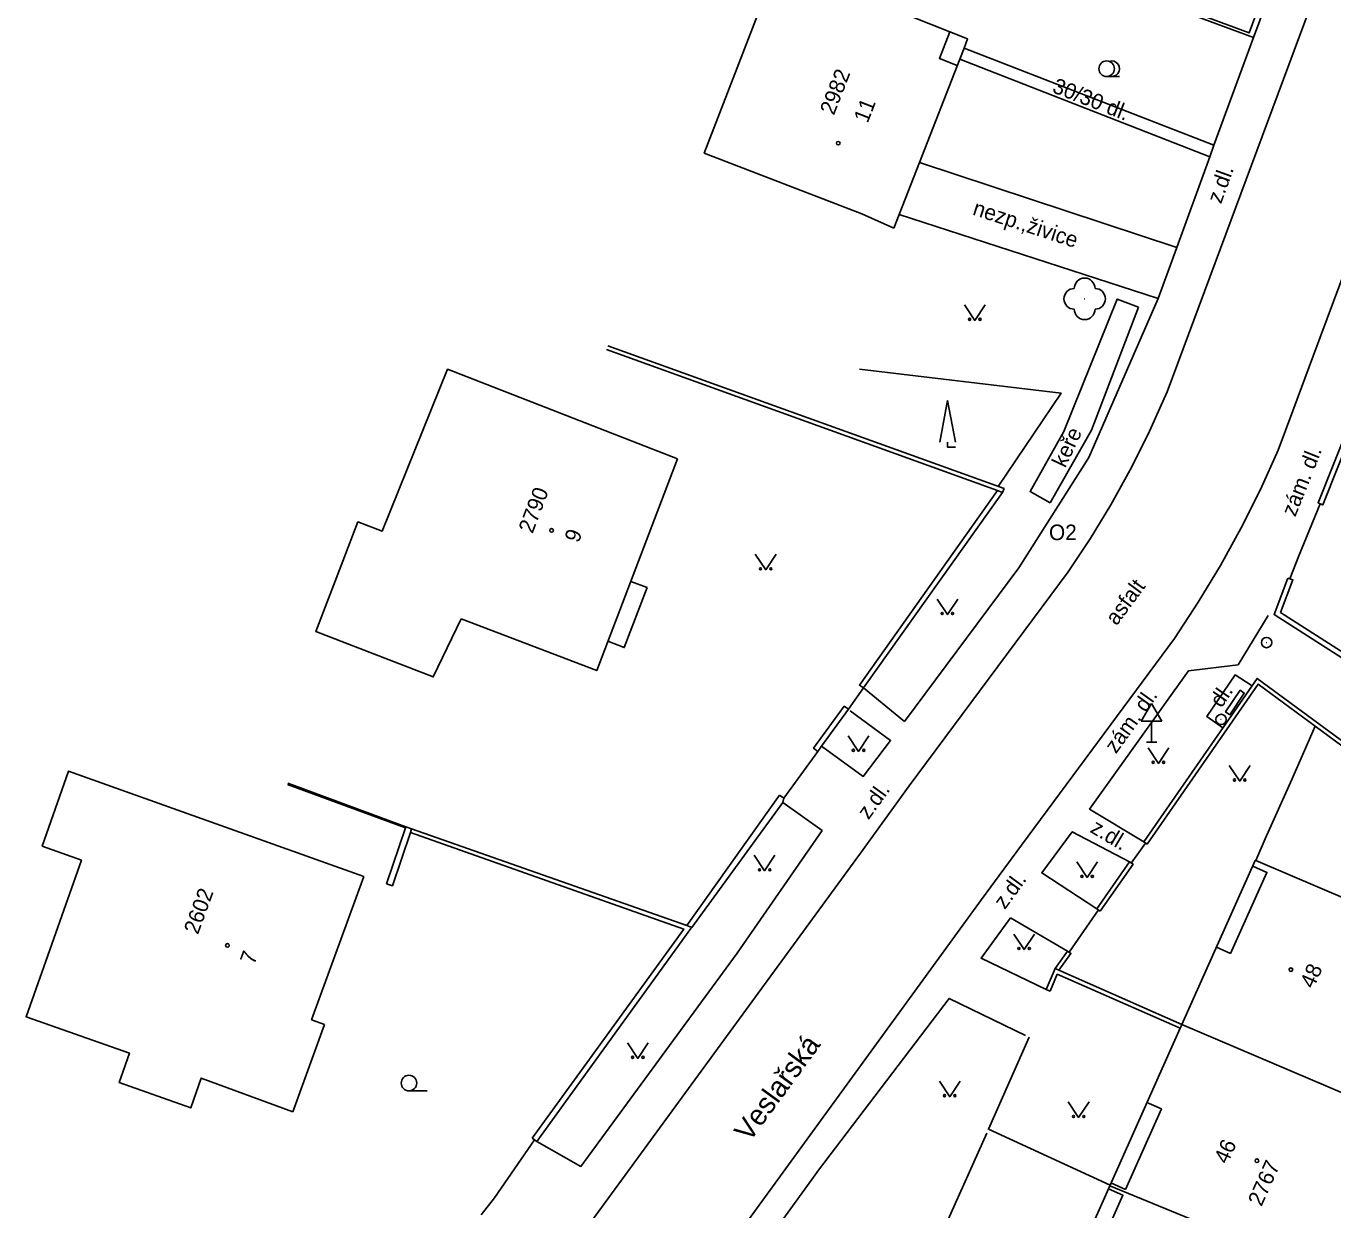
# Model space of a CAD drawing. Extents: x -584400 to -581602, y -1210894 to -1208793.
# Drawn here: x -583267.9 to -583204.8, y -1210484 to -1210426.9 of the extents above; entities that cross this region are included whole.
import ezdxf

# ---------------------------------------------------------------- set-up
doc = ezdxf.new("R2010")
doc.units = 0
for name, color, linetype in [('BUDOVY_MĚŘ', 7, 'Continuous'), ('NÁZVY_ULIC_TOK_SMĚR', 7, 'Continuous'), ('POMOC_POPIS', 7, 'Continuous'), ('ROZHRANÍ_PLOCH', 7, 'Continuous'), ('ZELEŇ', 7, 'Continuous'), ('ZN_BUDOV', 7, 'Continuous'), ('ZN_DOPLŇKOVÉ', 7, 'Continuous'), ('ZN_KULTUR', 7, 'Continuous'), ('Č_POPIS_EVID', 7, 'Continuous')]:
    doc.layers.add(name, color=color, linetype=linetype)

msp = doc.modelspace()

# ---------------------------------------------------------------- linework, layer by layer
at = {"layer": 'BUDOVY_MĚŘ'}
for points in [[(-583223.3, -1210427.13), (-583231.61, -1210423.81), (-583235.14, -1210432.98), (-583227.54, -1210435.91), (-583226, -1210436.6)], [(-583222.61, -1210427.91), (-583222.44, -1210427.47), (-583223.3, -1210427.13)], [(-583222.82, -1210428.45), (-583222.61, -1210427.91)], [(-583226, -1210436.6), (-583225.74, -1210435.94), (-583224.76, -1210433.43), (-583222.82, -1210428.45)], [(-583236.44, -1210447.73), (-583247.53, -1210443.41), (-583250.69, -1210451.22), (-583251.85, -1210450.77), (-583252.58, -1210452.66), (-583253.89, -1210456.06), (-583248.22, -1210458.25), (-583246.87, -1210455.45)], [(-583246.87, -1210455.45), (-583240.33, -1210457.94), (-583236.44, -1210447.73)], [(-583251.57, -1210467.88), (-583265.81, -1210462.79), (-583267.08, -1210466.41), (-583265.19, -1210467.08), (-583267.86, -1210474.64), (-583262.87, -1210476.4), (-583263.37, -1210477.82), (-583259.92, -1210479.04), (-583259.41, -1210477.6), (-583255, -1210479.23)], [(-583212.14, -1210475.1), (-583212.1, -1210475.01), (-583208.56, -1210467.1), (-583208.53, -1210467.11)], [(-583208.53, -1210467.11), (-583197.95, -1210471.63), (-583201.46, -1210479.55)], [(-583255, -1210479.23), (-583253.47, -1210475.02), (-583254.09, -1210474.79), (-583251.57, -1210467.88)], [(-583215.56, -1210482.76), (-583212.18, -1210475.19)], [(-583212.18, -1210475.19), (-583212.14, -1210475.1)], [(-583201.46, -1210479.55), (-583212.1, -1210475.01)], [(-583218.9, -1210490.28), (-583215.64, -1210482.94), (-583215.58, -1210482.8)], [(-583215.58, -1210482.8), (-583215.56, -1210482.76)], [(-583204.85, -1210487.2), (-583215.58, -1210482.8)]]:
    msp.add_lwpolyline(points, dxfattribs=at)
at = {"layer": 'ROZHRANÍ_PLOCH'}
for points in [[(-583176.25, -1210363.59), (-583205.75, -1210442.72)], [(-583212.81, -1210444.5), (-583187.79, -1210377.24)], [(-583222.94, -1210428.75), (-583223.8, -1210428.41), (-583223.3, -1210427.13)], [(-583210.55, -1210432.6), (-583222.61, -1210427.91)], [(-583208.64, -1210427.4), (-583210.55, -1210432.6)], [(-583210.75, -1210433.16), (-583222.82, -1210428.45)], [(-583210.55, -1210432.6), (-583210.75, -1210433.16)], [(-583212.34, -1210437.54), (-583224.76, -1210433.43)], [(-583210.75, -1210433.16), (-583212.34, -1210437.54)], [(-583213.25, -1210440), (-583225.74, -1210435.94)], [(-583212.34, -1210437.54), (-583213.25, -1210440)], [(-583213.25, -1210440), (-583216.59, -1210447.66), (-583219.97, -1210452.98), (-583225.48, -1210460.4)], [(-583206.75, -1210445.41), (-583205.75, -1210442.72)], [(-583217.59, -1210453.18), (-583216.52, -1210451.58), (-583215.52, -1210449.94), (-583214.59, -1210448.26), (-583213.72, -1210446.54), (-583212.81, -1210444.5)], [(-583212.45, -1210456.39), (-583211.31, -1210454.65), (-583210.24, -1210452.87), (-583209.24, -1210451.06), (-583208.31, -1210449.2), (-583207.45, -1210447.31), (-583206.75, -1210445.41)], [(-583217.59, -1210453.18), (-583225.26, -1210463.51), (-583227.61, -1210466.75), (-583239.44, -1210482.95), (-583241.75, -1210486.11), (-583261.42, -1210513.13), (-583262.5, -1210514.29)], [(-583238.69, -1210453.64), (-583237.9, -1210453.94)], [(-583239.8, -1210456.53), (-583239, -1210456.83), (-583237.9, -1210453.94)], [(-583209.39, -1210457.66), (-583207.94, -1210455.29)], [(-583212.45, -1210456.39), (-583219.83, -1210466.36), (-583221.77, -1210468.99)], [(-583213.94, -1210466.21), (-583216.55, -1210464.62), (-583211.78, -1210457.96), (-583209.39, -1210457.66)], [(-583210.13, -1210460.7), (-583210.9, -1210460.15), (-583209.53, -1210458.15), (-583208.71, -1210458.68)], [(-583225.48, -1210460.4), (-583227.46, -1210458.78)], [(-583228.1, -1210459.88), (-583226.15, -1210461.32), (-583227.47, -1210463.05), (-583229.49, -1210461.59)], [(-583231.35, -1210464.31), (-583229.46, -1210465.66), (-583233.56, -1210471.58), (-583241.09, -1210481.86), (-583243.22, -1210480.66)], [(-583216.2, -1210469.44), (-583218.86, -1210467.7), (-583217.39, -1210465.72), (-583214.62, -1210467.17)], [(-583209.75, -1210471.59), (-583208, -1210467.68), (-583208.68, -1210467.37)], [(-583221.77, -1210468.99), (-583238.84, -1210492.46), (-583241.63, -1210496.27), (-583249.18, -1210506.55), (-583256.63, -1210516.77)], [(-583220.36, -1210469.87), (-583221.79, -1210471.81), (-583218.65, -1210473.32)], [(-583217.61, -1210471.47), (-583220.36, -1210469.87)], [(-583209.75, -1210471.59), (-583210.43, -1210471.29)], [(-583219.64, -1210475.55), (-583223.33, -1210473.76), (-583229.63, -1210482.04), (-583229.95, -1210482.49)], [(-583214.82, -1210482.97), (-583213.09, -1210479.09), (-583213.79, -1210478.78)], [(-583227.53, -1210493.6), (-583235.45, -1210490.08), (-583229.95, -1210482.49)], [(-583214.82, -1210482.97), (-583215.52, -1210482.66)], [(-583216.57, -1210486.92), (-583214.94, -1210483.25), (-583215.64, -1210482.94)]]:
    msp.add_lwpolyline(points, dxfattribs=at)
at = {"layer": 'ZELEŇ'}
for points in [[(-583218.46, -1210449.85), (-583219.42, -1210449.31), (-583217.79, -1210446.41), (-583215.22, -1210440.02), (-583214.19, -1210440.41)], [(-583220.96, -1210449.06), (-583217.93, -1210444.56), (-583227.65, -1210443.4)]]:
    msp.add_lwpolyline(points, dxfattribs=at)
msp.add_circle((-583216.79, -1210440.01), 0.0005, dxfattribs=at)
for centre, start, end in [((-583216.79, -1210439.51), 0, 179.99999), ((-583217.29, -1210440.01), 89.99999, 269.99999), ((-583216.29, -1210440.01), 270, 89.99999), ((-583216.79, -1210440.51), 179.99999, 359.99999)]:
    msp.add_arc(centre, 0.5, start, end, dxfattribs=at)
at = {"layer": 'ZN_BUDOV'}
for centre in [(-583228.68, -1210432.5), (-583242.51, -1210451.18), (-583258.15, -1210471.2), (-583206.84, -1210472.37), (-583208.48, -1210481.59)]:
    msp.add_circle(centre, 0.0875, dxfattribs=at)
at = {"layer": 'ZN_DOPLŇKOVÉ'}
for p, q in [((-583213.56, -1210459.524), (-583214.06, -1210460.39)), ((-583213.56, -1210459.524), (-583213.06, -1210460.39)), ((-583214.06, -1210460.39), (-583213.06, -1210460.39)), ((-583213.56, -1210461.39), (-583213.56, -1210460.39)), ((-583213.81, -1210461.39), (-583213.31, -1210461.39))]:
    msp.add_line(p, q, dxfattribs=at)
for points in [[(-583218.05, -1210423.91), (-583208.64, -1210427.4), (-583205.74, -1210419.58), (-583206, -1210419.48)], [(-583218, -1210423.79), (-583208.85, -1210427.18), (-583206, -1210419.48)], [(-583214.19, -1210440.41), (-583216.46, -1210446.34), (-583218.46, -1210449.85)], [(-583220.99, -1210449.26), (-583239.86, -1210442.46)], [(-583220.68, -1210449.16), (-583239.8, -1210442.28)], [(-583204.08, -1210446.22), (-583205.53, -1210449.85), (-583205.42, -1210449.9)], [(-583203.85, -1210446.31), (-583205.3, -1210449.95), (-583205.42, -1210449.9)], [(-583220.99, -1210449.26), (-583227.66, -1210458.64), (-583227.46, -1210458.78)], [(-583220.75, -1210449.35), (-583227.46, -1210458.78)], [(-583220.75, -1210449.35), (-583220.99, -1210449.26)], [(-583220.68, -1210449.16), (-583220.75, -1210449.35)], [(-583205.42, -1210449.9), (-583206.45, -1210452.4)], [(-583206.45, -1210452.4), (-583206.89, -1210453.52)], [(-583206.98, -1210453.48), (-583207.65, -1210455.24), (-583200.31, -1210459.93)], [(-583206.98, -1210453.48), (-583206.74, -1210453.57), (-583207.34, -1210455.14), (-583200.17, -1210459.72)], [(-583228.19, -1210459.81), (-583227.46, -1210458.78)], [(-583200.46, -1210464.21), (-583208.47, -1210458.32), (-583213.94, -1210466.21), (-583213.77, -1210466.32)], [(-583205.67, -1210460.62), (-583208.42, -1210458.6), (-583213.77, -1210466.32)], [(-583209.79, -1210460.08), (-583209.99, -1210459.94), (-583209.29, -1210458.89), (-583209.09, -1210459.03), (-583209.79, -1210460.08)], [(-583228.19, -1210459.81), (-583228.39, -1210459.66), (-583229.87, -1210461.69), (-583229.67, -1210461.84)], [(-583228.19, -1210459.81), (-583229.49, -1210461.59), (-583229.67, -1210461.84)], [(-583205.67, -1210460.62), (-583206.8, -1210463.2)], [(-583178.76, -1210480.24), (-583200.58, -1210464.37), (-583205.67, -1210460.62)], [(-583231.3, -1210464.09), (-583229.67, -1210461.84)], [(-583206.8, -1210463.2), (-583208.08, -1210466.06)], [(-583255.25, -1210463.43), (-583249.56, -1210465.53)], [(-583255.23, -1210463.37), (-583249.54, -1210465.48)], [(-583231.51, -1210463.95), (-583235.99, -1210470.24)], [(-583231.51, -1210463.95), (-583231.3, -1210464.09)], [(-583231.3, -1210464.09), (-583231.35, -1210464.31), (-583235.75, -1210470.33)], [(-583249.56, -1210465.53), (-583250.48, -1210468.23)], [(-583249.32, -1210465.76), (-583250.19, -1210468.32), (-583250.48, -1210468.23)], [(-583249.54, -1210465.48), (-583249.56, -1210465.53)], [(-583249.26, -1210465.57), (-583249.54, -1210465.48)], [(-583249.26, -1210465.57), (-583249.32, -1210465.76)], [(-583243.44, -1210480.5), (-583236.13, -1210470.41), (-583249.32, -1210465.76)], [(-583235.99, -1210470.24), (-583249.26, -1210465.57)], [(-583213.86, -1210466.26), (-583214.54, -1210467.23)], [(-583208.08, -1210466.06), (-583208.53, -1210467.11)], [(-583214.62, -1210467.17), (-583216.2, -1210469.44), (-583216.04, -1210469.55)], [(-583214.62, -1210467.17), (-583214.45, -1210467.28), (-583216.04, -1210469.55)], [(-583216.12, -1210469.49), (-583217.53, -1210471.53)], [(-583235.75, -1210470.33), (-583235.99, -1210470.24)], [(-583243.22, -1210480.66), (-583235.79, -1210470.39), (-583235.75, -1210470.33)], [(-583217.61, -1210471.47), (-583218.22, -1210472.32)], [(-583217.61, -1210471.47), (-583217.45, -1210471.59), (-583218.03, -1210472.4)], [(-583218.22, -1210472.32), (-583218.65, -1210473.32), (-583218.46, -1210473.4)], [(-583218.11, -1210472.58), (-583218.46, -1210473.4)], [(-583218.22, -1210472.32), (-583218.03, -1210472.4)], [(-583218.11, -1210472.58), (-583212.18, -1210475.19)], [(-583218.03, -1210472.4), (-583212.1, -1210475.01)], [(-583215.56, -1210482.76), (-583221.43, -1210480.07), (-583219.46, -1210475.63)], [(-583223.46, -1210484.6), (-583221.51, -1210480.25)], [(-583245.26, -1210483.37), (-583243.33, -1210480.58)], [(-583243.44, -1210480.5), (-583243.22, -1210480.66)], [(-583245.26, -1210483.37), (-583245.91, -1210484.2)]]:
    msp.add_lwpolyline(points, dxfattribs=at)
for centre, radius in [((-583208.01, -1210456.59), 0.25), ((-583208.01, -1210456.59), 0.0005), ((-583210.21, -1210460.3), 0.25), ((-583210.21, -1210460.3), 0.0005)]:
    msp.add_circle(centre, radius, dxfattribs=at)
at = {"layer": 'ZN_KULTUR'}
for p, q in [((-583215.73, -1210429.285), (-583215.105, -1210429.285)), ((-583249.39, -1210478.215), (-583248.515, -1210478.215))]:
    msp.add_line(p, q, dxfattribs=at)
for points in [[(-583222.59, -1210440.3), (-583222.09, -1210441.05), (-583221.59, -1210440.3)], [(-583223.775, -1210446.92), (-583223.4, -1210444.92), (-583223.025, -1210446.92)], [(-583223.4, -1210446.92), (-583223.4, -1210447.17), (-583223.025, -1210447.17)], [(-583232.68, -1210452.33), (-583232.18, -1210453.08), (-583231.68, -1210452.33)], [(-583223.91, -1210454.49), (-583223.41, -1210455.24), (-583222.91, -1210454.49)], [(-583228.2, -1210461.09), (-583227.7, -1210461.84), (-583227.2, -1210461.09)], [(-583213.73, -1210461.67), (-583213.23, -1210462.42), (-583212.73, -1210461.67)], [(-583209.81, -1210462.52), (-583209.31, -1210463.27), (-583208.81, -1210462.52)], [(-583232.73, -1210466.85), (-583232.23, -1210467.6), (-583231.73, -1210466.85)], [(-583217.17, -1210467.17), (-583216.67, -1210467.92), (-583216.17, -1210467.17)], [(-583220.21, -1210470.65), (-583219.71, -1210471.4), (-583219.21, -1210470.65)], [(-583238.85, -1210475.9), (-583238.35, -1210476.65), (-583237.85, -1210475.9)], [(-583223.8, -1210477.75), (-583223.3, -1210478.5), (-583222.8, -1210477.75)], [(-583217.58, -1210478.75), (-583217.08, -1210479.5), (-583216.58, -1210478.75)]]:
    msp.add_lwpolyline(points, dxfattribs=at)
for centre, radius in [((-583215.73, -1210428.91), 0.375), ((-583222.34, -1210441), 0.05), ((-583221.84, -1210441), 0.05), ((-583232.43, -1210453.03), 0.05), ((-583231.93, -1210453.03), 0.05), ((-583223.66, -1210455.19), 0.05), ((-583223.16, -1210455.19), 0.05), ((-583227.95, -1210461.79), 0.05), ((-583227.45, -1210461.79), 0.05), ((-583213.48, -1210462.37), 0.05), ((-583212.98, -1210462.37), 0.05), ((-583209.56, -1210463.22), 0.05), ((-583209.06, -1210463.22), 0.05), ((-583232.48, -1210467.55), 0.05), ((-583231.98, -1210467.55), 0.05), ((-583216.92, -1210467.87), 0.05), ((-583216.42, -1210467.87), 0.05), ((-583219.96, -1210471.35), 0.05), ((-583219.46, -1210471.35), 0.05), ((-583238.6, -1210476.6), 0.05), ((-583238.1, -1210476.6), 0.05), ((-583249.39, -1210477.84), 0.375), ((-583223.55, -1210478.45), 0.05), ((-583223.05, -1210478.45), 0.05), ((-583217.33, -1210479.45), 0.05), ((-583216.83, -1210479.45), 0.05)]:
    msp.add_circle(centre, radius, dxfattribs=at)
msp.add_arc((-583215.48, -1210428.91), 0.375, 249.49437, 109.04743, dxfattribs=at)

# ---------------------------------------------------------------- texts
at = {"layer": 'NÁZVY_ULIC_TOK_SMĚR'}
msp.add_text('Veslařská', height=1, rotation=53.83907, dxfattribs=at).set_placement((-583232.96, -1210480.73))
at = {"layer": 'POMOC_POPIS'}
for s, rotation, p in [('30/30 dl.', 338.68309, (-583218.4, -1210430.03)), ('z.dl.', 69.95339, (-583210.21, -1210435.46)), ('nezp.,živice', 341.99272, (-583222.24, -1210435.94)), ('zám. dl.', 68.19859, (-583206.63, -1210450.56)), ('asfalt', 53.49037, (-583215.25, -1210455.81)), ('dl.', 55.58888, (-583210.19, -1210459.78)), ('zám. dl.', 54.38916, (-583215.28, -1210461.99)), ('z.dl.', 54.04631, (-583227.22, -1210465.17)), ('z.dl.', 329.25598, (-583216.57, -1210465.71)), ('z.dl.', 53.97119, (-583220.64, -1210469.5))]:
    msp.add_text(s, height=0.75, rotation=rotation, dxfattribs=at).set_placement(p)
msp.add_text('O2', height=0.75, dxfattribs=at).set_placement((-583218.51, -1210451.65))
at = {"layer": 'ZELEŇ'}
msp.add_text('keře', height=0.75, rotation=64.68934, dxfattribs=at).set_placement((-583217.73, -1210448.2))
at = {"layer": 'Č_POPIS_EVID'}
for s, rotation, p in [('2982', 68.72193, (-583228.89, -1210431.19)), ('11', 68.72193, (-583227.26, -1210431.57)), ('2790', 69.14879, (-583243.43, -1210451.37)), ('9', 69.14879, (-583241.21, -1210451.82)), ('2602', 69.93242, (-583259.57, -1210470.71)), ('7', 69.93242, (-583256.86, -1210472.17)), ('48', 65.90453, (-583205.75, -1210473.32)), ('46', 65.93759, (-583209.9, -1210481.79)), ('2767', 65.93759, (-583208.26, -1210483.83))]:
    msp.add_text(s, height=0.75, rotation=rotation, dxfattribs=at).set_placement(p)

doc.saveas('drawing.dxf')
